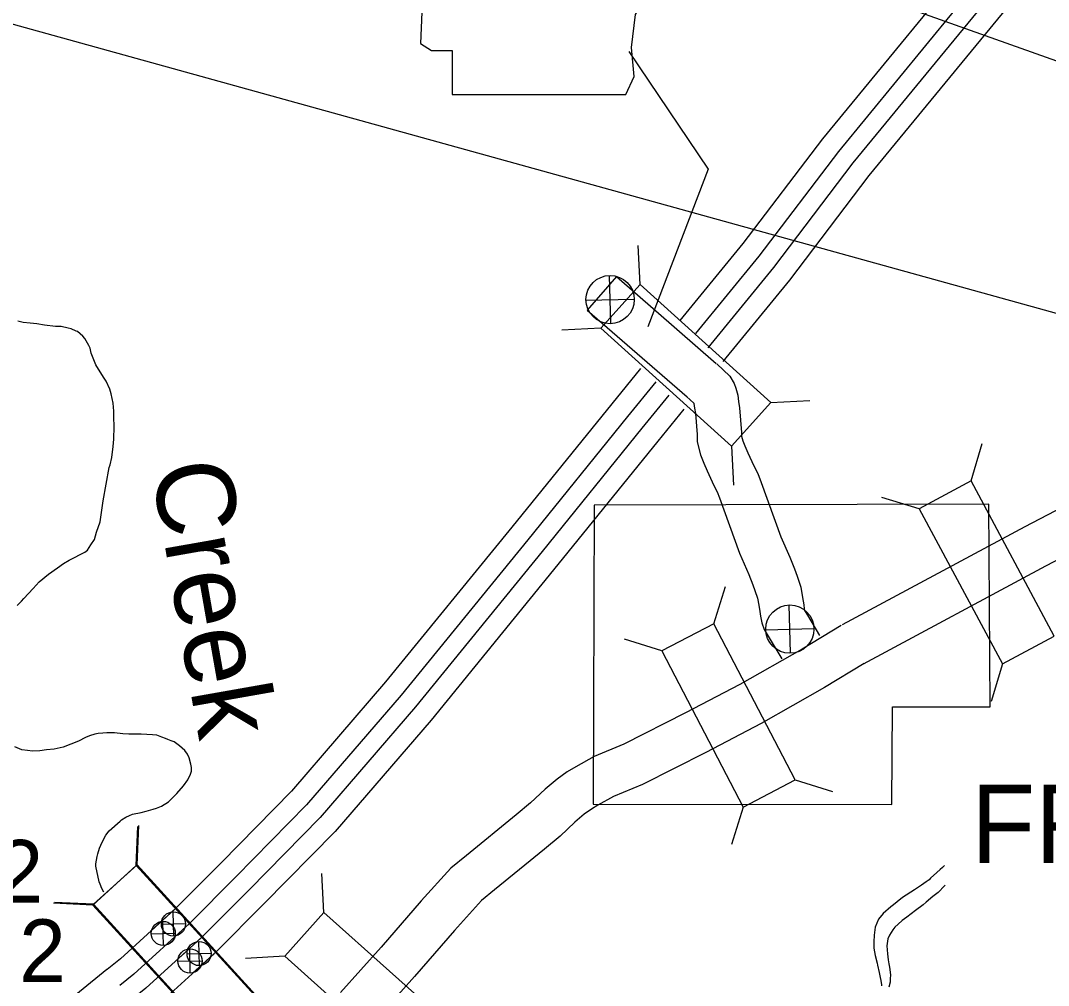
# Model space of a CAD drawing. Extents: x 1373862 to 1377080, y 1164775 to 1170415.
# Drawn here: x 1374357.1 to 1374426.4, y 1170012.7 to 1170077.8 of the extents above; entities that cross this region are included whole.
import ezdxf

# ---------------------------------------------------------------- set-up
doc = ezdxf.new("R2010")
doc.units = 0
doc.layers.add('1', color=7, linetype='Continuous')
doc.layers.add('Default', color=7, linetype='Continuous')

msp = doc.modelspace()

# ---------------------------------------------------------------- linework, layer by layer
at = {"layer": '1'}
for p in [(1374172.843, 1170165.768), (1374199.554, 1170121.066)]:
    msp.add_line(p, (1374640.758, 1169998.763), dxfattribs=at)
at = {"layer": 'Default'}
for p, q in [((1374398.101, 1170075.694), (1374403.472, 1170067.745)), ((1374403.472, 1170067.745), (1374399.39, 1170057.109)), ((1374398.868, 1170059.966), (1374398.731, 1170062.603)), ((1374397.272, 1170060.51), (1374395.303, 1170058.247)), ((1374396.885, 1170057.326), (1374396.81, 1170060.581)), ((1374395.22, 1170058.916), (1374398.474, 1170058.991)), ((1374396.216, 1170057.025), (1374393.58, 1170056.888)), ((1374407.692, 1170052.012), (1374410.328, 1170052.149)), ((1374405.041, 1170049.071), (1374405.178, 1170046.435)), ((1374421.193, 1170046.715), (1374421.954, 1170049.243)), ((1374417.704, 1170044.842), (1374415.176, 1170045.603)), ((1374403.841, 1170037.08), (1374404.632, 1170039.598)), ((1374409.01, 1170035.094), (1374408.934, 1170038.349)), ((1374407.345, 1170036.684), (1374410.599, 1170036.759)), ((1374400.33, 1170035.247), (1374397.811, 1170036.038)), ((1374423.323, 1170034.375), (1374422.562, 1170031.847)), ((1374409.338, 1170026.548), (1374411.857, 1170025.757)), ((1374405.827, 1170024.716), (1374405.036, 1170022.197)), ((1374364.87, 1170020.775), (1374364.992, 1170023.412)), ((1374364.931, 1170020.83), (1374365.053, 1170023.467)), ((1374377.537, 1170017.603), (1374377.392, 1170020.239)), ((1374361.944, 1170018.107), (1374359.307, 1170018.229)), ((1374362.005, 1170018.162), (1374359.367, 1170018.284)), ((1374367.406, 1170016.018), (1374367.369, 1170017.646)), ((1374366.574, 1170016.813), (1374368.201, 1170016.851)), ((1374366.718, 1170015.378), (1374366.681, 1170017.006)), ((1374365.886, 1170016.173), (1374367.513, 1170016.211)), ((1374368.526, 1170013.518), (1374368.489, 1170015.145)), ((1374369.137, 1170014.022), (1374369.1, 1170015.65)), ((1374367.694, 1170014.313), (1374369.321, 1170014.35)), ((1374368.305, 1170014.817), (1374369.932, 1170014.855)), ((1374374.895, 1170014.653), (1374372.259, 1170014.508))]:
    msp.add_line(p, q, dxfattribs=at)
for points in [[(1374383.584, 1170090.28), (1374384.422, 1170084.697), (1374384.05, 1170076.23), (1374384.794, 1170075.765), (1374386.19, 1170075.765), (1374386.19, 1170072.787), (1374397.914, 1170072.787), (1374398.472, 1170073.997), (1374398.286, 1170075.951), (1374398.565, 1170078.184), (1374399.589, 1170079.952), (1374400.24, 1170081.254), (1374401.171, 1170082.65), (1374401.729, 1170084.139), (1374402.194, 1170085.349), (1374403.032, 1170086.372), (1374403.218, 1170087.023), (1374402.846, 1170087.489), (1374399.961, 1170087.489), (1374400.612, 1170088.791), (1374400.705, 1170089.629), (1374400.32, 1170090.272)], [(1374407.692, 1170052.012), (1374398.868, 1170059.966), (1374396.216, 1170057.025), (1374405.041, 1170049.071)], [(1374417.704, 1170044.842), (1374423.323, 1170034.375), (1374426.812, 1170036.248), (1374421.193, 1170046.715)], [(1374400.33, 1170035.247), (1374405.827, 1170024.716), (1374409.338, 1170026.548), (1374403.841, 1170037.08)], [(1374372.874, 1170011.995), (1374364.87, 1170020.775), (1374361.944, 1170018.107), (1374369.947, 1170009.327)], [(1374362.005, 1170018.162), (1374370.008, 1170009.383), (1374372.935, 1170012.05), (1374364.931, 1170020.83)], [(1374386.387, 1170009.678), (1374377.537, 1170017.603), (1374374.895, 1170014.653), (1374383.745, 1170006.728)]]:
    msp.add_lwpolyline(points, close=True, dxfattribs=at)
for points in [[(1374422.931, 1170084.131), (1374411.166, 1170069.802)], [(1374423.993, 1170083.258), (1374412.245, 1170068.95)], [(1374424.96, 1170082.465), (1374413.226, 1170068.175)], [(1374426.022, 1170081.592), (1374414.305, 1170067.322)], [(1374411.166, 1170069.802), (1374405.799, 1170062.742), (1374401.544, 1170057.54)], [(1374412.245, 1170068.95), (1374406.879, 1170061.89), (1374402.613, 1170056.675)], [(1374413.226, 1170068.175), (1374407.861, 1170061.116), (1374403.43, 1170055.699)], [(1374414.305, 1170067.322), (1374408.94, 1170060.264), (1374404.46, 1170054.787)], [(1374500.092, 1170057.6), (1374486.398, 1170060.629), (1374477.286, 1170062.522), (1374470.214, 1170064.001), (1374469.167, 1170064.167), (1374468.747, 1170064.264), (1374468.097, 1170064.351), (1374467.5, 1170064.488), (1374466.957, 1170064.534), (1374466.414, 1170064.538), (1374465.839, 1170064.446), (1374465.41, 1170064.364), (1374464.671, 1170064.16), (1374463.704, 1170063.811), (1374462.762, 1170063.376), (1374459.24, 1170061.608), (1374441.614, 1170052.381), (1374424.822, 1170043.624), (1374412.497, 1170037.007)], [(1374499.31, 1170054.701), (1374485.769, 1170057.696), (1374476.674, 1170059.585), (1374469.671, 1170061.049), (1374468.594, 1170061.221), (1374468.211, 1170061.309), (1374467.561, 1170061.396), (1374467.034, 1170061.517), (1374466.817, 1170061.535), (1374466.641, 1170061.536), (1374466.36, 1170061.491), (1374466.093, 1170061.44), (1374465.581, 1170061.299), (1374464.844, 1170061.033), (1374464.064, 1170060.673), (1374460.608, 1170058.938), (1374443.004, 1170049.722), (1374426.225, 1170040.972), (1374413.916, 1170034.364)], [(1374397.272, 1170060.51), (1374404.012, 1170054.646)], [(1374395.303, 1170058.247), (1374402.043, 1170052.382)], [(1374356.851, 1170038.305), (1374357.142, 1170038.604), (1374357.303, 1170038.793), (1374357.916, 1170039.459), (1374358.338, 1170039.917), (1374358.97, 1170040.424), (1374359.562, 1170040.86), (1374359.983, 1170041.138), (1374360.363, 1170041.366), (1374360.724, 1170041.554), (1374361.094, 1170041.752), (1374361.405, 1170041.92), (1374361.595, 1170042.059), (1374361.817, 1170042.398), (1374362.059, 1170042.776), (1374362.192, 1170043.256), (1374362.436, 1170043.965), (1374362.654, 1170045.384), (1374363.048, 1170047.614), (1374363.119, 1170047.803), (1374363.232, 1170048.303), (1374363.326, 1170049.033), (1374363.369, 1170049.543), (1374363.385, 1170050.383), (1374363.379, 1170051.024), (1374363.361, 1170051.424), (1374363.325, 1170051.965), (1374363.199, 1170052.586), (1374363.101, 1170052.917), (1374362.845, 1170053.459), (1374362.677, 1170053.72), (1374362.144, 1170054.544), (1374361.918, 1170055.105), (1374361.839, 1170055.336), (1374361.761, 1170055.667), (1374361.673, 1170055.847), (1374361.406, 1170056.319), (1374361.268, 1170056.49), (1374360.92, 1170056.793), (1374360.831, 1170056.833), (1374360.482, 1170056.985), (1374360.283, 1170057.027), (1374359.815, 1170057.13), (1374359.425, 1170057.132), (1374358.697, 1170057.226), (1374358.169, 1170057.31), (1374357.73, 1170057.372), (1374357.261, 1170057.405), (1374356.883, 1170057.498)], [(1374404.049, 1170054.612), (1374404.932, 1170053.791), (1374405.213, 1170053.298), (1374405.331, 1170052.982), (1374405.454, 1170052.51), (1374405.509, 1170052.071), (1374405.582, 1170051.655), (1374405.711, 1170049.988), (1374405.716, 1170049.749), (1374405.795, 1170049.425), (1374405.934, 1170049.096), (1374406.142, 1170048.605), (1374406.535, 1170047.748), (1374406.82, 1170047.223), (1374407.045, 1170046.605), (1374408.365, 1170042.955), (1374408.962, 1170041.57), (1374409.285, 1170040.782), (1374409.461, 1170040.288), (1374409.704, 1170039.541), (1374409.829, 1170038.853), (1374409.913, 1170038.361), (1374409.948, 1170038.087), (1374409.971, 1170037.977), (1374410.156, 1170037.67), (1374410.982, 1170036.29)], [(1374398.905, 1170054.313), (1374396.956, 1170051.931), (1374390.226, 1170043.606), (1374381.706, 1170033.155), (1374375.351, 1170025.789), (1374370.63, 1170020.976), (1374367.536, 1170017.873), (1374365.851, 1170016.337)], [(1374399.931, 1170053.396), (1374398.023, 1170051.064), (1374391.293, 1170042.739), (1374382.76, 1170032.272), (1374376.364, 1170024.858), (1374371.608, 1170020.01), (1374368.486, 1170016.879), (1374366.993, 1170015.518)], [(1374400.817, 1170052.505), (1374398.993, 1170050.275), (1374392.264, 1170041.951), (1374383.718, 1170031.468), (1374377.284, 1170024.011), (1374372.497, 1170019.131), (1374369.351, 1170015.975), (1374367.878, 1170014.633)], [(1374402.006, 1170052.416), (1374402.498, 1170051.958), (1374402.501, 1170051.945), (1374402.541, 1170051.623), (1374402.603, 1170051.277), (1374402.714, 1170049.841), (1374402.724, 1170049.359), (1374402.937, 1170048.481), (1374403.171, 1170047.927), (1374403.396, 1170047.395), (1374403.85, 1170046.405), (1374404.078, 1170045.986), (1374404.225, 1170045.581), (1374405.574, 1170041.85), (1374406.196, 1170040.406), (1374406.482, 1170039.709), (1374406.621, 1170039.321), (1374406.789, 1170038.804), (1374406.875, 1170038.331), (1374406.945, 1170037.92), (1374406.987, 1170037.594), (1374407.078, 1170037.155), (1374407.241, 1170036.694), (1374407.585, 1170036.125), (1374408.424, 1170034.723)], [(1374401.821, 1170051.561), (1374400.06, 1170049.408), (1374393.331, 1170041.085), (1374384.771, 1170030.585), (1374378.296, 1170023.079), (1374373.474, 1170018.164), (1374370.301, 1170014.981), (1374368.683, 1170013.506)], [(1374422.391, 1170045.152), (1374395.777, 1170045.079), (1374395.734, 1170031.504), (1374395.712, 1170024.904), (1374415.855, 1170024.89)], [(1374415.855, 1170024.89), (1374415.891, 1170031.49), (1374422.491, 1170031.486), (1374422.391, 1170045.152)], [(1374412.427, 1170036.967), (1374409.8, 1170035.369), (1374405.595, 1170032.987), (1374401.932, 1170031.075), (1374397.762, 1170028.967), (1374395.764, 1170028.128), (1374394.528, 1170027.442), (1374393.943, 1170027.09), (1374393.266, 1170026.605), (1374392.467, 1170025.935), (1374391.472, 1170025), (1374390.509, 1170024.189), (1374387.158, 1170021.455), (1374386.107, 1170020.599), (1374384.099, 1170018.383), (1374381.402, 1170015.264), (1374378.663, 1170012.205)], [(1374413.986, 1170034.404), (1374411.319, 1170032.782), (1374407.029, 1170030.352), (1374403.303, 1170028.406), (1374399.022, 1170026.243), (1374397.077, 1170025.425), (1374396.029, 1170024.844), (1374395.592, 1170024.581), (1374395.107, 1170024.233), (1374394.46, 1170023.691), (1374393.467, 1170022.758), (1374392.424, 1170021.879), (1374389.053, 1170019.13), (1374388.178, 1170018.417), (1374386.346, 1170016.394), (1374383.654, 1170013.282), (1374380.885, 1170010.19)], [(1374367.014, 1170029.277), (1374366.845, 1170029.348), (1374366.606, 1170029.43), (1374366.267, 1170029.572), (1374365.978, 1170029.584), (1374365.219, 1170029.628), (1374364.86, 1170029.641), (1374364.371, 1170029.644), (1374363.982, 1170029.656), (1374363.404, 1170029.719), (1374363.214, 1170029.721), (1374362.905, 1170029.723), (1374362.635, 1170029.704), (1374362.305, 1170029.676), (1374362.096, 1170029.627), (1374361.736, 1170029.53), (1374361.465, 1170029.421), (1374360.985, 1170029.164), (1374359.954, 1170028.75), (1374359.345, 1170028.633), (1374358.815, 1170028.567), (1374358.386, 1170028.509), (1374357.877, 1170028.492), (1374357.547, 1170028.524), (1374357.168, 1170028.577), (1374356.681, 1170028.77)], [(1374362.699, 1170018.976), (1374362.559, 1170019.218), (1374362.441, 1170019.509), (1374362.382, 1170019.679), (1374362.159, 1170020.731), (1374362.16, 1170020.891), (1374362.243, 1170021.391), (1374362.284, 1170021.561), (1374362.406, 1170021.95), (1374362.588, 1170022.34), (1374362.831, 1170022.818), (1374363.062, 1170023.117), (1374363.795, 1170023.773), (1374363.885, 1170023.853), (1374364.186, 1170024.041), (1374364.436, 1170024.15), (1374364.636, 1170024.238), (1374365.206, 1170024.355), (1374365.556, 1170024.433), (1374366.026, 1170024.58), (1374366.236, 1170024.649), (1374366.576, 1170024.777), (1374367.057, 1170025.064), (1374367.348, 1170025.353), (1374367.619, 1170025.621), (1374368.062, 1170026.149), (1374368.354, 1170026.547), (1374368.546, 1170026.926), (1374368.597, 1170027.146), (1374368.609, 1170027.376), (1374368.56, 1170027.617), (1374368.453, 1170028.028), (1374368.335, 1170028.289), (1374368.147, 1170028.54), (1374367.809, 1170028.842), (1374367.442, 1170029.114), (1374367.243, 1170029.176), (1374367.014, 1170029.277)], [(1374419.403, 1170020.782), (1374419.26, 1170020.639), (1374419.113, 1170020.516), (1374418.887, 1170020.312), (1374418.466, 1170019.913), (1374418.368, 1170019.811), (1374418.171, 1170019.677), (1374417.847, 1170019.44), (1374417.374, 1170019.13), (1374416.565, 1170018.613), (1374416.222, 1170018.326), (1374415.956, 1170018.121), (1374415.779, 1170017.997), (1374415.269, 1170017.526), (1374414.947, 1170017.16), (1374414.719, 1170016.614), (1374414.659, 1170016.083), (1374414.649, 1170015.622), (1374414.647, 1170015.191), (1374414.727, 1170014.713), (1374414.857, 1170014.195), (1374414.89, 1170014.055), (1374415, 1170013.567), (1374415.076, 1170013.228), (1374415.12, 1170013.018), (1374415.156, 1170012.729), (1374415.148, 1170012.649)], [(1374419.439, 1170019.447), (1374419.395, 1170019.411), (1374418.975, 1170018.952), (1374418.611, 1170018.674)], [(1374418.611, 1170018.674), (1374418.179, 1170018.305), (1374417.973, 1170018.111), (1374417.452, 1170017.73), (1374416.871, 1170017.298), (1374416.546, 1170017.071), (1374416.272, 1170016.826), (1374416.046, 1170016.621), (1374415.92, 1170016.428), (1374415.698, 1170016.073), (1374415.583, 1170015.821), (1374415.523, 1170015.349), (1374415.553, 1170014.819), (1374415.602, 1170014.41), (1374415.647, 1170014.15), (1374415.701, 1170013.921), (1374415.752, 1170013.391), (1374415.747, 1170013.131), (1374415.742, 1170012.901), (1374415.649, 1170012.569)], [(1374367.468, 1170017.811), (1374363.823, 1170014.488), (1374362.911, 1170013.757)], [(1374368.462, 1170016.856), (1374364.717, 1170013.443), (1374363.772, 1170012.684)], [(1374369.263, 1170015.896), (1374365.53, 1170012.493), (1374364.554, 1170011.709)], [(1374370.131, 1170014.826), (1374366.425, 1170011.447), (1374365.414, 1170010.637)], [(1374362.901, 1170013.749), (1374359.209, 1170010.747)]]:
    msp.add_lwpolyline(points, dxfattribs=at)
for centre, radius in [((1374396.847, 1170058.953), 1.628), ((1374408.972, 1170036.721), 1.628), ((1374367.387, 1170016.832), 0.814), ((1374366.7, 1170016.192), 0.814), ((1374368.508, 1170014.332), 0.814), ((1374369.119, 1170014.836), 0.814)]:
    msp.add_circle(centre, radius, dxfattribs=at)

# ---------------------------------------------------------------- texts
msp.add_text('Creek', height=5.28, rotation=280, dxfattribs=at).set_placement((1374365.864, 1170047.678))
for s, height, p in [('FRIENDSHIP', 5.28, (1374421.203, 1170020.939)), ('2', 4.224, (1374355.464, 1170018.274)), ('2', 4.224, (1374356.985, 1170012.914))]:
    msp.add_text(s, height=height, dxfattribs=at).set_placement(p)

doc.saveas('drawing.dxf')
